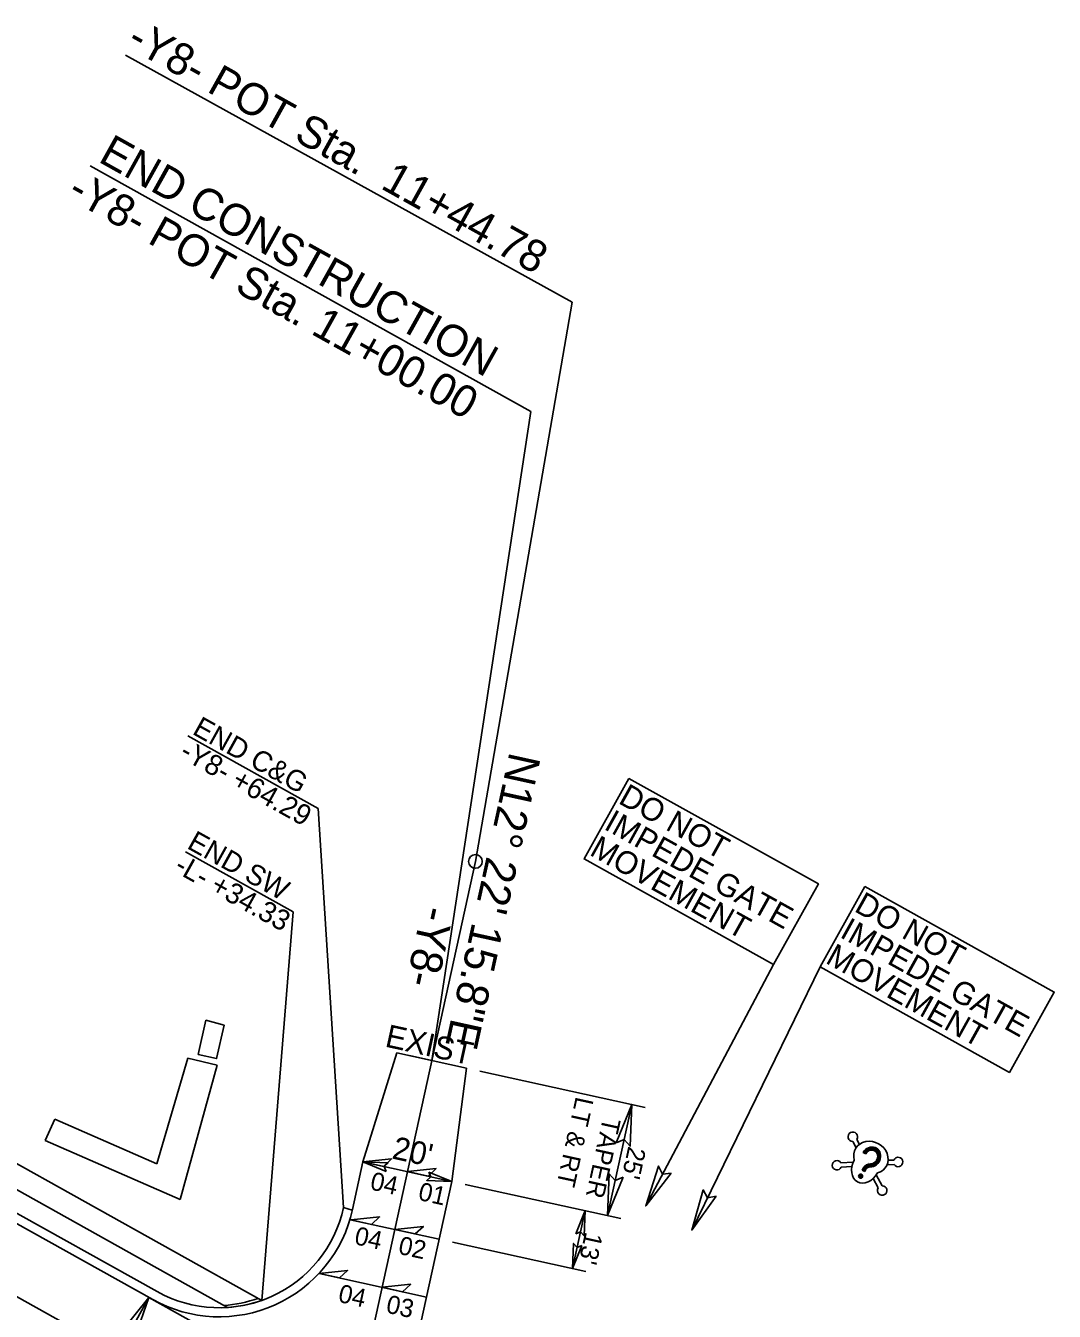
# Model space of a CAD drawing. Extents: x 1762196 to 1766326, y 709922 to 713142.
# Drawn here: x 1764978 to 1765204.1, y 710745.3 to 711027.8 of the extents above; entities that cross this region are included whole.
import ezdxf

# ---------------------------------------------------------------- set-up
doc = ezdxf.new("R2010")
doc.units = 0
for name, color, linetype in [('Old_Level_20', 7, 'Continuous'), ('Pattern 1', 7, 'Continuous'), ('Pattern 2', 7, 'Continuous'), ('Prop Conc 2ft 6in Curb and Gutter', 7, 'Continuous'), ('Prop Dimension', 7, 'Continuous'), ('Prop EOT', 7, 'Continuous'), ('Prop Horizontal Alignment', 7, 'Continuous'), ('Prop Horizontal Alignment Direction Label', 7, 'Continuous'), ('Prop Horizontal Alignment Station Label', 7, 'Continuous'), ('Prop Horizontal Alignment Tick Small', 7, 'Continuous'), ('Prop Lane Lines', 7, 'Continuous'), ('Prop Superelevation  Arrow CELL', 7, 'Continuous'), ('Prop Superelevation Label', 7, 'Continuous'), ('Prop Terminator CELL', 7, 'Continuous')]:
    doc.layers.add(name, color=color, linetype=linetype)

msp = doc.modelspace()

# ---------------------------------------------------------------- linework, layer by layer
at = {"layer": 'Old_Level_20'}
for p, q in [((1765006.88, 710777.69), (1765013.7, 710800.9)), ((1765020.11, 710799.37), (1765013.7, 710800.9)), ((1765020.11, 710799.37), (1765011.99, 710769.85)), ((1764982.35, 710782.86), (1764984.41, 710787.55)), ((1764984.41, 710787.55), (1765006.88, 710777.69)), ((1765011.99, 710769.85), (1764982.35, 710782.86))]:
    msp.add_line(p, q, dxfattribs=at)
msp.add_lwpolyline([(1765021.64, 710808.14), (1765020, 710800.83), (1765015.97, 710801.73), (1765017.66, 710809.26)], close=True, dxfattribs=at)
at = {"layer": 'Pattern 1'}
for p, q in [((1764581.02, 710998.13), (1765029.9, 710747.7)), ((1765022.41, 710746.16), (1764578.58, 710993.76))]:
    msp.add_line(p, q, dxfattribs=at)
msp.add_arc((1765020.56, 710774.1), 28, 273.7788, 289.4892, dxfattribs=at)
at = {"layer": 'Pattern 2'}
for p, q in [((1764581.02, 710998.13), (1765029.9, 710747.7)), ((1764578.58, 710993.76), (1765022.41, 710746.16))]:
    msp.add_line(p, q, dxfattribs=at)
msp.add_arc((1765019.75, 710774.55), 28, 273.7788, 289.4892, dxfattribs=at)
at = {"layer": 'Prop Conc 2ft 6in Curb and Gutter'}
for p, q in [((1764576.39, 710989.83), (1765006.92, 710749.64)), ((1765047.91, 710768.1), (1765049.82, 710767.51))]:
    msp.add_line(p, q, dxfattribs=at)
msp.add_arc((1765020.56, 710774.1), 28, 240.8436, 347.6289, dxfattribs=at)
at = {"layer": 'Prop Dimension'}
for p, q in [((1765042.31, 710855.81), (1765013.7, 710871.74)), ((1765042.31, 710855.81), (1765047.91, 710768.1)), ((1765036.83, 710833.09), (1765013.19, 710846.23)), ((1765029.9, 710747.7), (1765036.83, 710833.09)), ((1765142.39, 710821.51), (1765114.29, 710768.45)), ((1765152.61, 710820.97), (1765124.4, 710763.16)), ((1765077.86, 710798.09), (1765114.17, 710790.12)), ((1765105.88, 710766.35), (1765111.24, 710790.77)), ((1765160.67, 710783.09), (1765161.27, 710781.99)), ((1765159.81, 710782.62), (1765160.56, 710781.26)), ((1765071.7, 710773.84), (1765052.16, 710778.13)), ((1765159.9, 710778.08), (1765157.2, 710777.94)), ((1765162.1, 710780.2), (1765162.64, 710779.89)), ((1765163.19, 710778.03), (1765163.19, 710778.03)), ((1765168.87, 710777.57), (1765167.32, 710777.49)), ((1765168.82, 710778.54), (1765167.57, 710778.48)), ((1765159.6, 710777.09), (1765157.25, 710776.96)), ((1765162.16, 710776.81), (1765161.89, 710776.34)), ((1765161.89, 710776.34), (1765162.43, 710776.03)), ((1765162.23, 710776.77), (1765161.97, 710776.29)), ((1765162.31, 710776.73), (1765162.04, 710776.25)), ((1765162.39, 710776.68), (1765162.12, 710776.21)), ((1765162.46, 710776.64), (1765162.2, 710776.16)), ((1765162.54, 710776.6), (1765162.28, 710776.12)), ((1765162.62, 710776.55), (1765162.35, 710776.08)), ((1765162.7, 710776.51), (1765162.43, 710776.03)), ((1765164.96, 710775.26), (1765166.26, 710772.89)), ((1765108.81, 710765.7), (1765074.63, 710773.2)), ((1765164.27, 710774.48), (1765165.4, 710772.42)), ((1765005.13, 710748.35), (1764985.67, 710713.4))]:
    msp.add_line(p, q, dxfattribs=at)
for points in [[(1765110.61, 710862.38), (1765152.23, 710839.19), (1765142.39, 710821.51), (1765100.76, 710844.7)], [(1765162.45, 710838.65), (1765204.08, 710815.46), (1765194.23, 710797.78), (1765152.61, 710820.97)]]:
    msp.add_lwpolyline(points, close=True, dxfattribs=at)
for radius in [0.443, 0.345, 0.244, 0.146, 0.0472]:
    msp.add_circle((1765161.52, 710775), radius, dxfattribs=at)
for centre, start, end in [((1765159.8, 710783.66), 326.7494, 270.6579), ((1765156.31, 710777.4), 31.0456, 334.9541), ((1765169.76, 710778.11), 211.0456, 154.9541), ((1765166.27, 710771.85), 146.7494, 90.6579)]:
    msp.add_arc(centre, 1.04, start, end, dxfattribs=at)
for centre, major_axis, ratio, start_param, end_param in [((1765163.79, 710779.1), (3.4, -1.89), 0.885014, 5.564242, 10.143721), ((1765163.85, 710779.22), (1.09, 1.95), 0.9, 3.567618, 7.853982), ((1765163.85, 710779.22), (1.04, 1.86), 0.9, 3.567618, 7.853982), ((1765163.85, 710779.22), (0.99, 1.78), 0.9, 3.567618, 7.853982), ((1765163.85, 710779.22), (0.94, 1.69), 0.9, 3.567618, 7.853982), ((1765163.85, 710779.22), (0.9, 1.6), 0.9, 3.567618, 7.853982), ((1765163.85, 710779.22), (0.85, 1.52), 0.9, 3.567618, 7.853982), ((1765163.85, 710779.22), (0.8, 1.43), 0.9, 3.567618, 7.853982), ((1765163.85, 710779.22), (0.75, 1.35), 0.9, 3.567618, 7.853982), ((1765162.7, 710777.16), (-1.89, -3.4), 0.752542, 4.722735, 7.843636), ((1765163.47, 710776.08), (0.82, 1.46), 0.9, 0.426026, 1.570796), ((1765163.47, 710776.08), (0.77, 1.38), 0.9, 0.426026, 1.570796), ((1765163.47, 710776.08), (0.72, 1.29), 0.9, 0.426026, 1.570796), ((1765163.47, 710776.08), (0.67, 1.2), 0.9, 0.426026, 1.570796), ((1765163.47, 710776.08), (0.62, 1.12), 0.9, 0.426026, 1.570796), ((1765163.47, 710776.08), (0.58, 1.03), 0.9, 0.426026, 1.570796), ((1765163.47, 710776.08), (0.527, 0.946), 0.9, 0.426026, 1.570796), ((1765163.47, 710776.08), (0.479, 0.86), 0.9, 0.426026, 1.570796)]:
    msp.add_ellipse(centre, major_axis=major_axis, ratio=ratio, start_param=start_param, end_param=end_param, dxfattribs=at)
at = {"layer": 'Prop EOT'}
for p, q in [((1764575.41, 710988.08), (1765005.95, 710747.9)), ((1765059.63, 710802.09), (1765052.16, 710778.13)), ((1765074.93, 710798.73), (1765059.63, 710802.09)), ((1765074.93, 710798.73), (1765071.7, 710773.84)), ((1765049.87, 710767.67), (1765052.16, 710778.13)), ((1765064.23, 710739.81), (1765071.7, 710773.84))]:
    msp.add_line(p, q, dxfattribs=at)
msp.add_arc((1765020.56, 710774.1), 30, 240.8436, 347.6289, dxfattribs=at)
at = {"layer": 'Prop Horizontal Alignment'}
msp.add_line((1765045.86, 710702.73), (1765076.88, 710844.14), dxfattribs=at)
at = {"layer": 'Prop Horizontal Alignment Station Label'}
for p, q in [((1764999.95, 711021.26), (1765098.15, 710967.04)), ((1764992.21, 710996.97), (1765089.06, 710943.03)), ((1765098.15, 710967.04), (1765076.88, 710844.14)), ((1765089.06, 710943.03), (1765067.28, 710800.41))]:
    msp.add_line(p, q, dxfattribs=at)
msp.add_circle((1765076.88, 710844.14), 1.5, dxfattribs=at)
at = {"layer": 'Prop Horizontal Alignment Tick Small'}
msp.add_line((1765067.28, 710800.41), (1765062.4, 710801.48), dxfattribs=at)
at = {"layer": 'Prop Lane Lines'}
for p, q in [((1764568.59, 710975.86), (1765119.98, 710668.25)), ((1765005.13, 710748.35), (1765080.74, 710706.17))]:
    msp.add_line(p, q, dxfattribs=at)
at = {"layer": 'Prop Superelevation  Arrow CELL'}
for points in [[(1765052.16, 710778.13), (1765058.45, 710778.8), (1765056.68, 710777.14)], [(1765061.93, 710775.99), (1765068.22, 710776.66), (1765066.45, 710775)], [(1765049.54, 710765.4), (1765055.82, 710766.06), (1765054.05, 710764.4)], [(1765059.14, 710763.29), (1765065.43, 710763.96), (1765063.66, 710762.3)], [(1765042.5, 710753.63), (1765048.79, 710754.3), (1765047.02, 710752.64)], [(1765056.36, 710750.59), (1765062.65, 710751.26), (1765060.87, 710749.6)]]:
    msp.add_lwpolyline(points, close=True, dxfattribs=at)
at = {"layer": 'Prop Superelevation Label'}
for p, q in [((1765071.7, 710773.84), (1765052.16, 710778.13)), ((1765098.21, 710754.72), (1765101, 710767.42)), ((1765068.91, 710761.15), (1765049.37, 710765.43)), ((1765101.14, 710754.08), (1765071.84, 710760.5)), ((1765066.13, 710748.45), (1765042.5, 710753.63))]:
    msp.add_line(p, q, dxfattribs=at)
at = {"layer": 'Prop Terminator CELL'}
for points in [[(1765107.8, 710782.31), (1765111.24, 710790.77), (1765110.86, 710781.58), (1765109.55, 710783.05)], [(1765057.24, 710776.06), (1765052.16, 710778.13), (1765057.67, 710777.9), (1765056.79, 710777.11)], [(1765066.62, 710775.91), (1765071.7, 710773.84), (1765066.19, 710774.07), (1765067.07, 710774.86)], [(1765109.32, 710774.8), (1765105.88, 710766.35), (1765106.26, 710775.53), (1765107.58, 710774.06)], [(1765119.87, 710775.68), (1765114.29, 710768.45), (1765117.11, 710777.2), (1765117.99, 710775.43)], [(1765129.74, 710770.57), (1765124.4, 710763.16), (1765126.93, 710771.99), (1765127.86, 710770.26)], [(1765098.93, 710762.34), (1765101, 710767.42), (1765100.77, 710761.91), (1765099.98, 710762.79)], [(1765100.28, 710759.79), (1765098.21, 710754.72), (1765098.44, 710760.23), (1765099.23, 710759.35)], [(1764999.4, 710741.24), (1765005.13, 710748.35), (1765002.13, 710739.67), (1765001.29, 710741.45)]]:
    msp.add_lwpolyline(points, close=True, dxfattribs=at)

# ---------------------------------------------------------------- texts
at = {"layer": 'Prop Dimension'}
for s, height, rotation, p in [('END C&G', 4.5, 330.8875, (1765014.43, 710872.25)), ('-Y8- +64.29', 4.5, 330.8875, (1765011.58, 710867.13)), ('DO NOT ', 5, 330.8875, (1765108.05, 710857.04)), ('IMPEDE GATE', 5, 330.8875, (1765104.89, 710851.36)), ('END SW', 4.5, 330.9251, (1765013.26, 710847.15)), ('MOVEMENT', 5, 330.8875, (1765101.72, 710845.68)), ('-L- +34.33', 4.5, 330.9251, (1765010.42, 710842.04)), ('DO NOT ', 5, 330.8875, (1765159.89, 710833.31)), ('IMPEDE GATE', 5, 330.8875, (1765156.73, 710827.63)), ('MOVEMENT', 5, 330.8875, (1765153.57, 710821.95)), ('EXIST', 5.005, 347.6289, (1765056.8, 710803.5)), ('LT & RT', 4, 257.6289, (1765098.96, 710792.63)), ('TAPER', 4, 257.6289, (1765104.93, 710788.08)), ("20'", 5, 347.6289, (1765058.33, 710778.91)), ("25'", 4, 257.6289, (1765110.49, 710781.7))]:
    msp.add_text(s, height=height, rotation=rotation, dxfattribs=at).set_placement(p)
at = {"layer": 'Prop Horizontal Alignment Direction Label'}
for s, p in [('N12%%d 22\' 15.8"E', (1765084.41, 710868.41)), ('-Y8-', (1765065.32, 710834.68))]:
    msp.add_text(s, height=7, rotation=257.6289, dxfattribs=at).set_placement(p)
at = {"layer": 'Prop Horizontal Alignment Station Label'}
for s, p in [('-Y8- POT Sta.  11+44.78', (1764999.9, 711023.26)), ('END CONSTRUCTION', (1764993.75, 710998)), ('-Y8- POT Sta. 11+00.00', (1764986.86, 710990.04))]:
    msp.add_text(s, height=7, rotation=330.8875, dxfattribs=at).set_placement(p)
at = {"layer": 'Prop Superelevation Label'}
for s, rotation, p in [('04', 347.6289, (1765053.53, 710772.11)), ('01', 347.6289, (1765064.09, 710769.82)), ('04', 347.6289, (1765050.07, 710760.09)), ('02', 347.6289, (1765059.71, 710757.98)), ("13'", 257.6289, (1765101.01, 710762.92)), ('04', 347.6289, (1765046.51, 710747.42)), ('03', 347.6289, (1765057.02, 710745.06))]:
    msp.add_text(s, height=4, rotation=rotation, dxfattribs=at).set_placement(p)

doc.saveas('drawing.dxf')
